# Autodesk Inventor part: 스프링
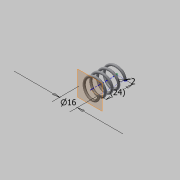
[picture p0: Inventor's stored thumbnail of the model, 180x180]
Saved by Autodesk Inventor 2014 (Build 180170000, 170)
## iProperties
Created: 2015-04
Part Number: 스프링
Material: Generic
Document SubType Name: Modeling
Designer: Administrator
Density: 1 g/cm^3
Appearance: Default
Mass: 0.606684 g
Surface Area: 12.5219 cm^2
Volume: 0.606684 cm^3
Author: Administrator
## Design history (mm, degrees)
sketch "스케치2"
  geometry: L1 (0, 11.5)-(-8, 11.5); L2 (-8, 11.5)-(-8, 0); L3 (-8, 0)-(0, 0); L4 (0, 0)-(0, 11.5); C1 r 1 at (-8, 0); 1 further point
  constraints: 8 end point, 2 coincident, 2 parallel, 1 centre point, 1 horizontal, 1 perpendicular
  dimensions: "d0" = 16 diameter of L2 L4; "d1" = 11.50049 distance between parallel lines of L1 L3 (derived); "d2" = 2 diameter of C1
feature "코일1" pitch "d3" = 10; turns "d5" = 4; dims "d4" = 11.50049 (= d1), "d6" = 0, angle "d7" = 90 deg, angle "d8" = 90 deg, "d9" = 0, "d10" = 0
sketch "스케치3"
  geometry: L1 (9, 0)-(7, 0) reference; 1 further point
  constraints: 1 horizontal alignment
extrude "돌출1" cut sketch "스케치3" stored distance "d11" = 10; taper "d12" = 0 deg
node "작업 평면1"
sketch "스케치4"
  geometry: L1 (7, 0)-(9, 0) reference; 1 further point
  constraints: 1 horizontal alignment
extrude "돌출2" cut sketch "스케치4" stored distance "d13" = 10; taper "d14" = 0 deg
node "솔리드1"
node "절단 모서리 투영1"
node "절단 모서리 투영2"
